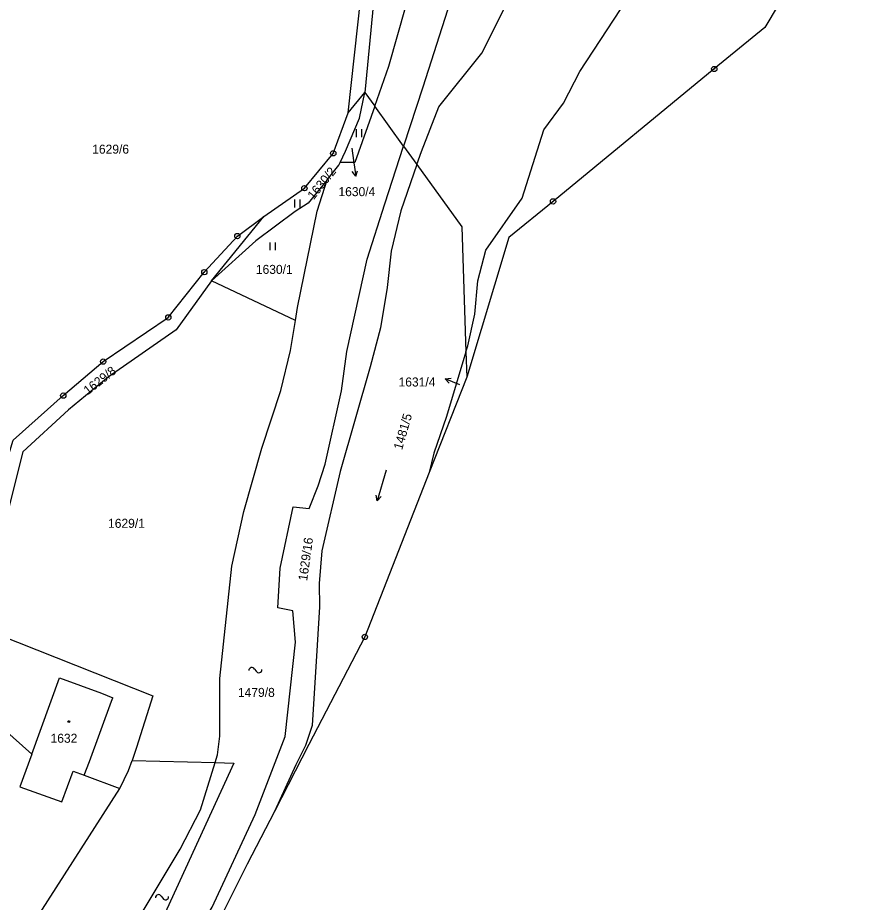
# Model space of a CAD drawing. Extents: x -562167 to -556918, y -1077891 to -1070763.
# Drawn here: x -559953.4 to -559792.8, y -1075869.3 to -1075702.3 of the extents above; entities that cross this region are included whole.
import ezdxf

# ---------------------------------------------------------------- set-up
doc = ezdxf.new("R2010")
doc.units = 0
for name, color, linetype in [('Hranice parcel', 7, 'Continuous'), ('Parcelní čísla', 7, 'Continuous'), ('Pop  PČ popisy', 7, 'Continuous'), ('Vnitřní kresba', 7, 'Continuous'), ('Značky bodu BP', 7, 'Continuous'), ('Značky budov', 7, 'Continuous'), ('Značky kultur', 7, 'Continuous')]:
    doc.layers.add(name, color=color, linetype=linetype)

msp = doc.modelspace()

# ---------------------------------------------------------------- linework, layer by layer
at = {"layer": 'Hranice parcel'}
for p, q in [((-559891.11, -1075720.29), (-559888.6, -1075697.43)), ((-559822.05, -1075711.99), (-559852.46, -1075736.97)), ((-559891.11, -1075720.29), (-559887.96, -1075716.42)), ((-559887.96, -1075716.42), (-559886.09, -1075719.02)), ((-559886.09, -1075719.02), (-559889.83, -1075729.64)), ((-559880.65, -1075726.57), (-559886.09, -1075719.02)), ((-559880.65, -1075726.57), (-559878.15, -1075730.03)), ((-559889.83, -1075729.64), (-559892.64, -1075729.62)), ((-559896.93, -1075738.82), (-559895.09, -1075732.88)), ((-559852.46, -1075736.97), (-559860.78, -1075743.81)), ((-559916.87, -1075751.94), (-559907.02, -1075739.84)), ((-559860.78, -1075743.81), (-559868.74, -1075770.18)), ((-559901.04, -1075759.48), (-559916.87, -1075751.94)), ((-559868.9, -1075765.37), (-559868.74, -1075770.18)), ((-559868.74, -1075770.18), (-559875.8, -1075788.17)), ((-559875.8, -1075788.17), (-559887.96, -1075819.17)), ((-559887.96, -1075819.17), (-559898.5, -1075839.5)), ((-559898.5, -1075839.5), (-559905.03, -1075852.11)), ((-559931.88, -1075842.47), (-559916.21, -1075842.88)), ((-559905.03, -1075852.11), (-559910.17, -1075862.03)), ((-559910.17, -1075862.03), (-559922.14, -1075886.1))]:
    msp.add_line(p, q, dxfattribs=at)
for points in [[(-559886.09, -1075719.02), (-559883.43, -1075711.48), (-559880.18, -1075699.93), (-559872.74, -1075676.56), (-559865.42, -1075650.17), (-559866.78, -1075644.07), (-559868.69, -1075640.78), (-559866.84, -1075636.53), (-559863.59, -1075633.88), (-559860.12, -1075628.22), (-559855.4, -1075617.21), (-559852.68, -1075611.71), (-559849.45, -1075604.61), (-559844.63, -1075595.88), (-559842.31, -1075591.31)], [(-559830.6, -1075592.95), (-559830.33, -1075593.67), (-559833.11, -1075596.14), (-559837.02, -1075601.09), (-559843.54, -1075614.23), (-559846.79, -1075622.8), (-559843.84, -1075624.67), (-559843.78, -1075625.66), (-559845.06, -1075628.9), (-559850.57, -1075638.13), (-559852.63, -1075644.86), (-559856.03, -1075660.05), (-559858.97, -1075667.66), (-559862.21, -1075667.29), (-559866.29, -1075679.71), (-559869.78, -1075692.79), (-559877, -1075715.45), (-559880.65, -1075726.57)], [(-559878.15, -1075730.03), (-559877.29, -1075727.54), (-559874, -1075719.14), (-559865.91, -1075709), (-559858.69, -1075694.56), (-559859.87, -1075690.66), (-559859.45, -1075688.67), (-559853.45, -1075676.96), (-559850.63, -1075669.86), (-559847.77, -1075660.52), (-559843.77, -1075641.43), (-559840.78, -1075625.79), (-559836.37, -1075610.95), (-559834.02, -1075605.09), (-559832.4, -1075602.14), (-559823.05, -1075594.01)], [(-559792.8, -1075649.37), (-559793.22, -1075666.45), (-559793.36, -1075671.85), (-559805.33, -1075692.07), (-559812.48, -1075704.13), (-559822.05, -1075711.99)], [(-559876.51, -1075656.33), (-559880.72, -1075668.86), (-559886.19, -1075698.06), (-559887.96, -1075716.42)], [(-559868.9, -1075765.37), (-559868.56, -1075764.24), (-559867.21, -1075758.23), (-559866.62, -1075751.98), (-559865.15, -1075746.21), (-559858.31, -1075736.37), (-559856.66, -1075731.24), (-559854.21, -1075723.5), (-559850.46, -1075718.45), (-559847.41, -1075712.45), (-559828.13, -1075682.93)], [(-559892.64, -1075729.62), (-559891.59, -1075727.51), (-559888.99, -1075721.26), (-559887.96, -1075716.42)], [(-559907.02, -1075739.84), (-559899.37, -1075734.49), (-559893.91, -1075727.91), (-559891.11, -1075720.29)], [(-559962.62, -1075941.04), (-559962.14, -1075939.89), (-559960.89, -1075940.1), (-559959.35, -1075938.75), (-559951.98, -1075927.24), (-559934.98, -1075901.05), (-559916.79, -1075870.18), (-559908.64, -1075852.68), (-559902.97, -1075837.98), (-559901.04, -1075820.14), (-559901.55, -1075814.24), (-559904.36, -1075813.68), (-559903.95, -1075806.2), (-559901.5, -1075794.65), (-559898.48, -1075794.96), (-559896.77, -1075790.65), (-559895.44, -1075786.56), (-559892.35, -1075772.75), (-559891.33, -1075765.33), (-559887.52, -1075747.86), (-559884.21, -1075737.42), (-559880.65, -1075726.57)], [(-559878.15, -1075730.03), (-559881.19, -1075738.79), (-559883, -1075746.39), (-559883.74, -1075753.2), (-559885.02, -1075760.82), (-559886.95, -1075768.23), (-559892.6, -1075787.96), (-559896.07, -1075802.91), (-559896.55, -1075809.06), (-559896.51, -1075813.48), (-559896.96, -1075820.72), (-559897.92, -1075835.87), (-559899.13, -1075839.66), (-559900.95, -1075843.29), (-559905.03, -1075852.11)], [(-559895.09, -1075732.88), (-559892.89, -1075730.12), (-559892.64, -1075729.62)], [(-559878.15, -1075730.03), (-559869.67, -1075741.79), (-559868.9, -1075765.37)], [(-559895.09, -1075732.88), (-559898.64, -1075737.32), (-559901.08, -1075738.9), (-559908.54, -1075744.41), (-559916.87, -1075751.94)], [(-559964.56, -1075815.78), (-559954.31, -1075782.02), (-559944.84, -1075773.63), (-559937.33, -1075767.22), (-559925.03, -1075758.87), (-559918.24, -1075750.34), (-559912.01, -1075743.52), (-559907.02, -1075739.84)], [(-559901.04, -1075759.48), (-559900.64, -1075757.03), (-559896.93, -1075738.82)], [(-559916.87, -1075751.94), (-559923.57, -1075761.23), (-559936.4, -1075770.16), (-559943.87, -1075776.29), (-559952.46, -1075784.22), (-559960.84, -1075817.26)], [(-559916.21, -1075842.88), (-559915.76, -1075841.43), (-559915.34, -1075837.91), (-559915.31, -1075827.02), (-559913.03, -1075805.84), (-559910.78, -1075795.47), (-559907.36, -1075783.52), (-559903.82, -1075772.66), (-559901.96, -1075765.1), (-559901.04, -1075759.48)], [(-559868.9, -1075765.37), (-559872.56, -1075777.58), (-559874.92, -1075784.46), (-559875.8, -1075788.17)], [(-559960.84, -1075817.26), (-559927.97, -1075830.29), (-559931.02, -1075840.03), (-559931.88, -1075842.47)], [(-559964.38, -1075829.19), (-559950.76, -1075841.28), (-559953.01, -1075847.45), (-559945.12, -1075850.32), (-559943.01, -1075844.52), (-559940.88, -1075845.27), (-559934.18, -1075847.79)], [(-559943.5, -1075893.96), (-559934.13, -1075878.11), (-559922.8, -1075859.21), (-559918.96, -1075851.8), (-559916.21, -1075842.88)], [(-559916.21, -1075842.88), (-559912.7, -1075842.97), (-559926.01, -1075872.07), (-559937.82, -1075891.38), (-559943.5, -1075893.96)], [(-559934.18, -1075847.79), (-559932.55, -1075844.36), (-559931.88, -1075842.47)], [(-559976.7, -1075902.62), (-559971.9, -1075903.77), (-559968.72, -1075901.59), (-559934.18, -1075847.79)]]:
    msp.add_lwpolyline(points, dxfattribs=at)
at = {"layer": 'Pop  PČ popisy'}
for p, q in [((-559890.43, -1075726.94), (-559890.11, -1075729.27)), ((-559890.11, -1075729.27), (-559889.69, -1075732.24)), ((-559889.69, -1075732.24), (-559890.33, -1075731.32)), ((-559889.69, -1075732.24), (-559889.34, -1075731.18)), ((-559872.81, -1075770.45), (-559871.7, -1075770.36)), ((-559870.03, -1075771.57), (-559872.81, -1075770.45)), ((-559872.81, -1075770.45), (-559872.07, -1075771.28))]:
    msp.add_line(p, q, dxfattribs=at)
at = {"layer": 'Vnitřní kresba'}
for p, q in [((-559950.76, -1075841.28), (-559945.53, -1075826.89)), ((-559945.53, -1075826.89), (-559937.65, -1075829.76)), ((-559937.65, -1075829.76), (-559935.49, -1075830.68)), ((-559939.93, -1075842.71), (-559935.72, -1075831.3)), ((-559935.72, -1075831.3), (-559935.49, -1075830.68)), ((-559940.88, -1075845.27), (-559939.93, -1075842.71))]:
    msp.add_line(p, q, dxfattribs=at)
at = {"layer": 'Značky bodu BP'}
for centre, radius in [((-559822.05, -1075711.99), 0.5), ((-559822.05, -1075711.99), 0.0303), ((-559893.91, -1075727.91), 0.5), ((-559893.91, -1075727.91), 0.0303), ((-559899.37, -1075734.49), 0.5), ((-559899.37, -1075734.49), 0.0303), ((-559852.46, -1075736.97), 0.5), ((-559852.46, -1075736.97), 0.0303), ((-559912.01, -1075743.52), 0.5), ((-559912.01, -1075743.52), 0.0303), ((-559918.24, -1075750.34), 0.5), ((-559918.24, -1075750.34), 0.0303), ((-559925.03, -1075758.87), 0.5), ((-559925.03, -1075758.87), 0.0303), ((-559937.33, -1075767.22), 0.5), ((-559937.33, -1075767.22), 0.0303), ((-559944.84, -1075773.63), 0.5), ((-559944.84, -1075773.63), 0.0303), ((-559887.96, -1075819.17), 0.5), ((-559887.96, -1075819.17), 0.0303)]:
    msp.add_circle(centre, radius, dxfattribs=at)
at = {"layer": 'Značky budov'}
for p, q in [((-559908.76, -1075825.23), (-559908.46, -1075825.63)), ((-559926.37, -1075868.09), (-559926.07, -1075868.49))]:
    msp.add_line(p, q, dxfattribs=at)
msp.add_circle((-559943.78, -1075835.15), 0.175, dxfattribs=at)
for centre, start, end in [((-559909.27, -1075825.52), 29.2914, 181.2189), ((-559907.95, -1075825.34), 209.2914, 1.2189), ((-559926.88, -1075868.38), 29.2914, 181.2189), ((-559925.56, -1075868.2), 209.2914, 1.2189)]:
    msp.add_arc(centre, 0.588, start, end, dxfattribs=at)
at = {"layer": 'Značky kultur'}
for p, q in [((-559889.54, -1075724.84), (-559889.54, -1075723.34)), ((-559888.54, -1075724.84), (-559888.54, -1075723.34)), ((-559901.19, -1075738.15), (-559901.19, -1075736.65)), ((-559900.19, -1075738.15), (-559900.19, -1075736.65)), ((-559905.8, -1075746.21), (-559905.8, -1075744.71)), ((-559904.8, -1075746.21), (-559904.8, -1075744.71)), ((-559883.96, -1075787.71), (-559885.61, -1075793.48)), ((-559885.61, -1075793.48), (-559885.82, -1075792.4)), ((-559885.61, -1075793.48), (-559884.86, -1075792.68))]:
    msp.add_line(p, q, dxfattribs=at)

# ---------------------------------------------------------------- texts
at = {"layer": 'Parcelní čísla'}
for s, p in [('1629/6', (-559939.39, -1075727.97)), ('1630/4', (-559892.94, -1075735.99)), ('1630/1', (-559908.52, -1075750.66)), ('1631/4', (-559881.6, -1075771.91)), ('1629/1', (-559936.4, -1075798.58)), ('1479/8', (-559911.9, -1075830.49)), ('1632', (-559947.25, -1075839.14))]:
    msp.add_text(s, height=1.7, dxfattribs=at).set_placement(p)
for s, rotation, p in [('1630/2', 51, (-559897.63, -1075736.78)), ('1629/8', 38, (-559940.2, -1075773.57)), ('1481/5', 74, (-559880.94, -1075783.98)), ('1629/16', 82, (-559898.85, -1075808.67))]:
    msp.add_text(s, height=1.7, rotation=rotation, dxfattribs=at).set_placement(p)

doc.saveas('drawing.dxf')
